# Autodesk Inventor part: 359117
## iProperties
Created: 2006-10
Part Number: 359117
Document SubType Name: Modeling
Designer: OSchmidt
Material: 1.0718.07
Description: Scheibe
Density: 7.84 g/cm^3
HalbzeugNorm: DIN 671
Zweck: 266464
Abmessung: Rd. 35
Author: Natti_01
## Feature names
1. Extrusion1
2. Bohrung1 [Hole]
3. Extrusion2
